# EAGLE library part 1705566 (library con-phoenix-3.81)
MKDSD 1,5/ 4-3,81 Printklemme Nennstrom: 8 A Bemessungsspannung: 200 V Raster: 3,81 mm Polzahl: 4 Montageart: Löten Anschlussart: Schraubanschluss Anschlussrichtung vom Leiter zur Platine: 0° Source: http://eshop.phoenixcontact.com .. 1705566.pdf
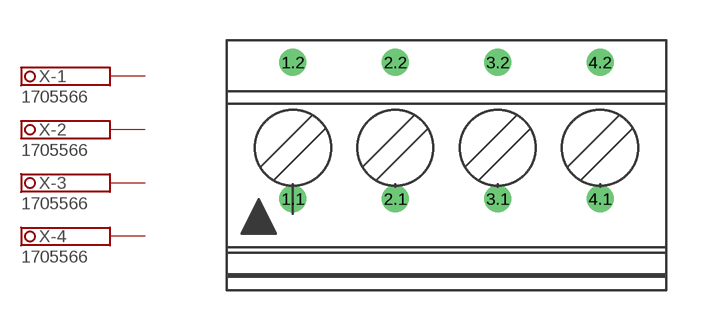
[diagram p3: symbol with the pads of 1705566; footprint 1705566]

Designator prefix X; gates -1=SCHRAUBKLEMME_2 -2=SCHRAUBKLEMME_2 -3=SCHRAUBKLEMME_2 -4=SCHRAUBKLEMME_2

## 1705566 (OC_FARNELL: unknown; OC_NEWARK: unknown)  [1705566]
1.1  -1:1A  pas
1.2  -1:1B  pas
2.1  -2:1A  pas
2.2  -2:1B  pas
3.1  -3:1A  pas
3.2  -3:1B  pas
4.1  -4:1A  pas
4.2  -4:1B  pas

## Footprint 1705566 (pad centres in mm)
MKDSD 1,5/ 4-3,81 Printklemme Nennstrom: 8 A Bemessungsspannung: 200 V Raster: 3,81 mm Polzahl: 4 Montageart: Löten Anschlussart: Schraubanschluss Anschlussrichtung vom Leiter zur Platine: 0° Source: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
drill 0.5 pad 0.9 round: 1.1 -5.715,-1.25; 1.2 -5.715,3.83; 2.1 -1.905,-1.25; 2.2 -1.905,3.83; 3.1 1.905,-1.25; 3.2 1.905,3.83; 4.1 5.715,-1.25; 4.2 5.715,3.83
